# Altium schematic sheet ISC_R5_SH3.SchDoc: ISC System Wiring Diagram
size B; DrawnBy: Filiberto Clara; Engineer: Filiberto Clara; Organization: LIGO Laboratory; Address1: California Institute of Technology; Address2: Massachusetts Institute of Technology; SheetNumber: 21; SheetTotal: 37
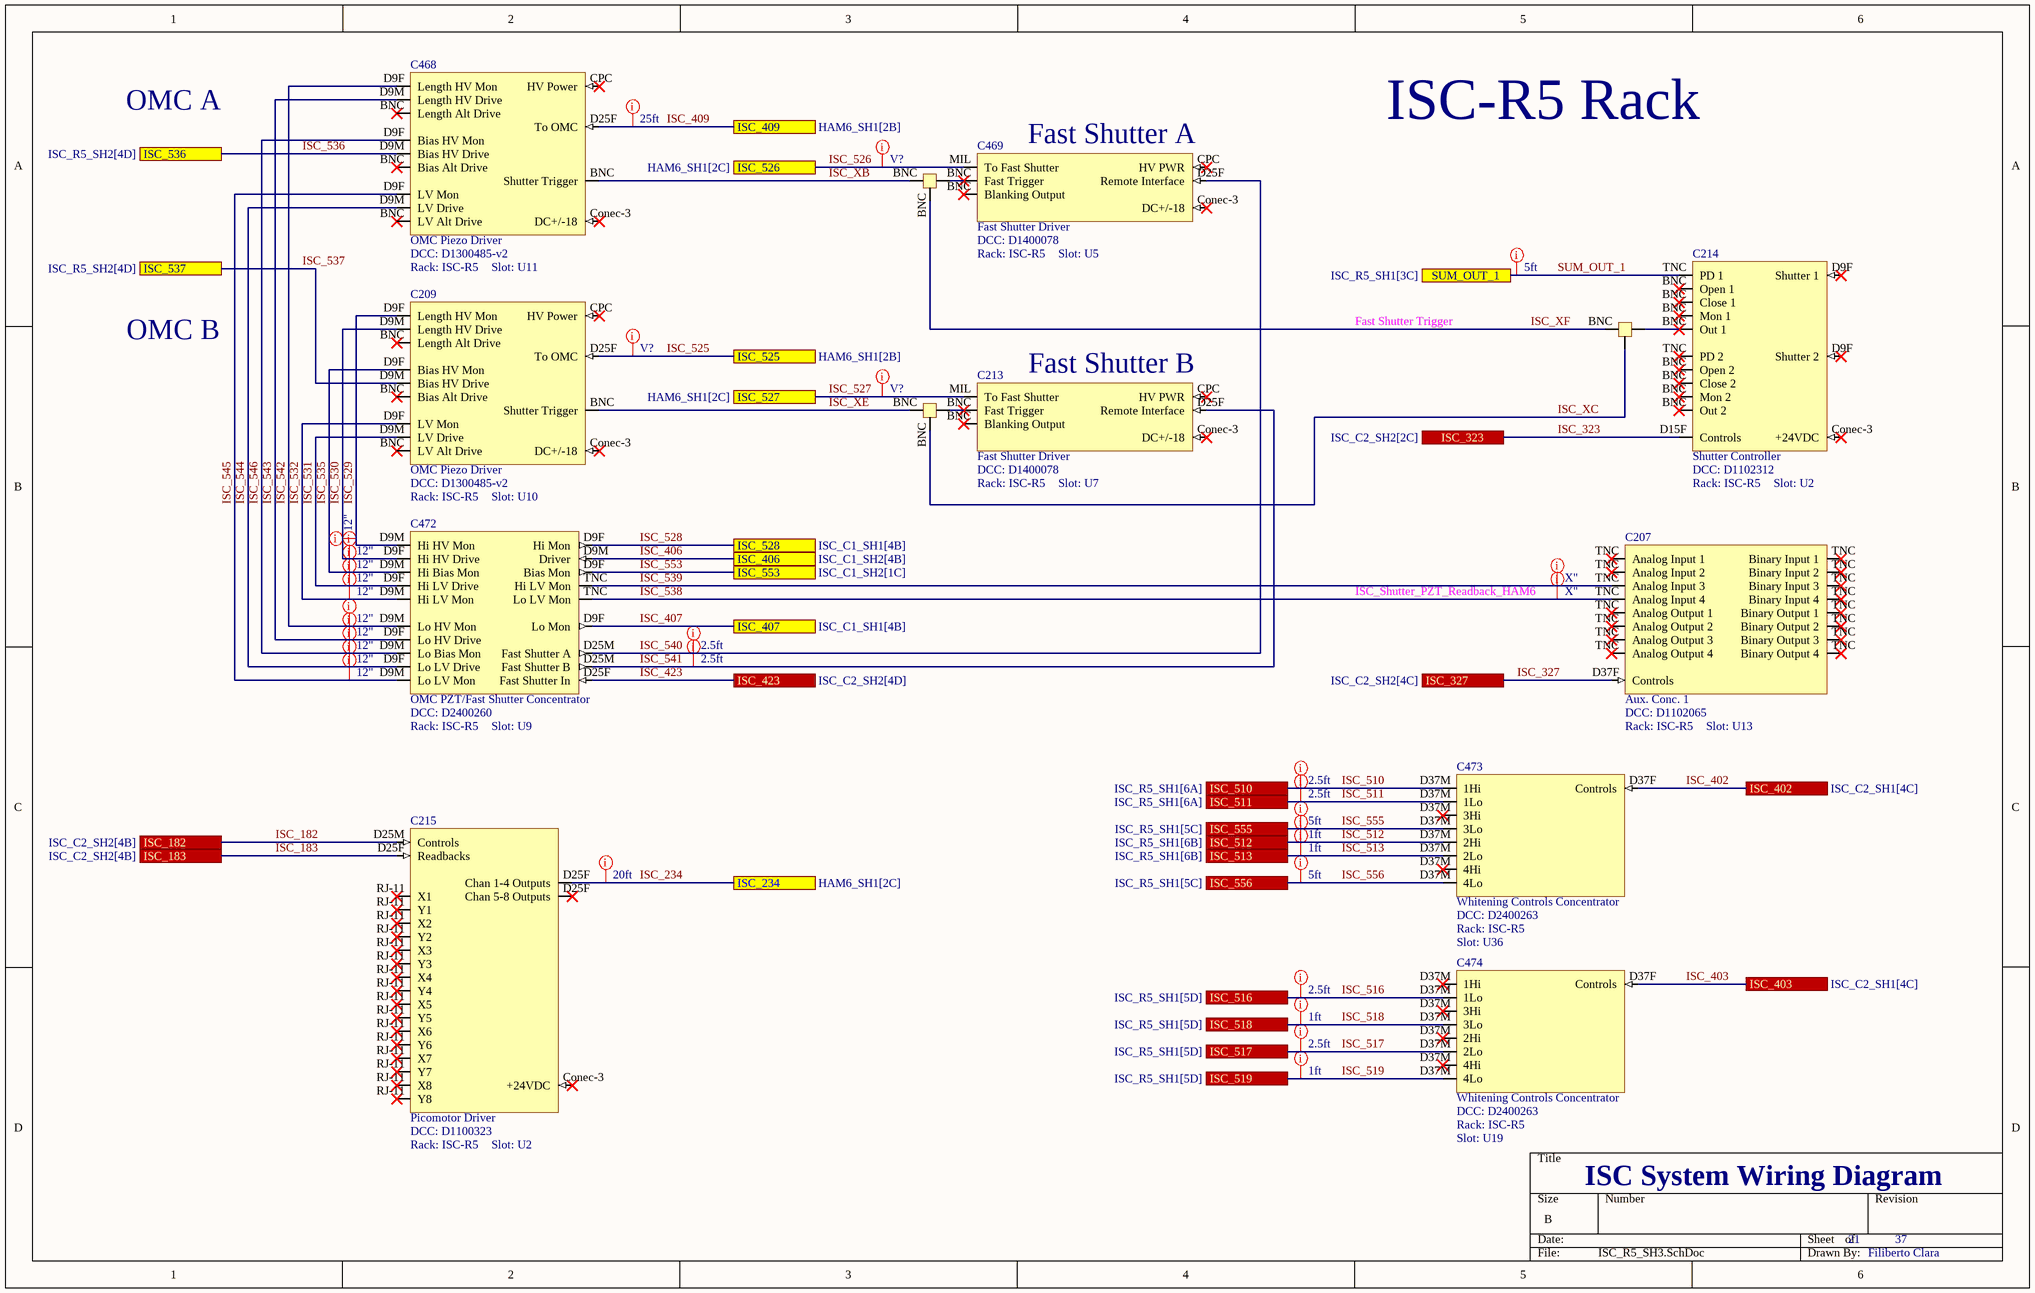
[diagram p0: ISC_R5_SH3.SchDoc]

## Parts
C207  Aux. Conc. 1  DCC: D1102065  Rack: ISC-R5  Slot: U13
C209  OMC Piezo Driver  DCC: D1300485-v2  Rack: ISC-R5  Slot: U10
C213  Fast Shutter Driver  DCC: D1400078  Rack: ISC-R5  Slot: U7
C214  Shutter Controller  DCC: D1102312  Rack: ISC-R5  Slot: U2
C215  Picomotor Driver  DCC: D1100323  Rack: ISC-R5  Slot: U2
C281  Tee  (value not drawn)
C468  OMC Piezo Driver  DCC: D1300485-v2  Rack: ISC-R5  Slot: U11
C469  Fast Shutter Driver  DCC: D1400078  Rack: ISC-R5  Slot: U5
C470  Tee  (value not drawn)
C471  Tee  (value not drawn)
C472  OMC PZT/Fast Shutter Concentrator  DCC: D2400260  Rack: ISC-R5  Slot: U9
C473  Whitening Controls Concentrator  DCC: D2400263  Rack: ISC-R5  Slot: U36
C474  Whitening Controls Concentrator  DCC: D2400263  Rack: ISC-R5  Slot: U19

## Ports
ISC_182 (see ISC_C2_SH2[4B]), ISC_183 (see ISC_C2_SH2[4B]), ISC_234 (see HAM6_SH1[2C]), ISC_323 (see ISC_C2_SH2[2C]), ISC_327 (see ISC_C2_SH2[4C]), ISC_402 (see ISC_C2_SH1[4C]), ISC_403 (see ISC_C2_SH1[4C]), ISC_406 (see ISC_C1_SH2[4B]), ISC_407 (see ISC_C1_SH1[4B]), ISC_409 (see HAM6_SH1[2B]), ISC_423 (see ISC_C2_SH2[4D]), ISC_510 (see ISC_R5_SH1[6A]), ISC_511 (see ISC_R5_SH1[6A]), ISC_512 (see ISC_R5_SH1[6B]), ISC_513 (see ISC_R5_SH1[6B]), ISC_516 (see ISC_R5_SH1[5D]), ISC_517 (see ISC_R5_SH1[5D]), ISC_518 (see ISC_R5_SH1[5D]), ISC_519 (see ISC_R5_SH1[5D]), ISC_525 (see HAM6_SH1[2B]), ISC_526 (see HAM6_SH1[2C]), ISC_527 (see HAM6_SH1[2C]), ISC_528 (see ISC_C1_SH1[4B]), ISC_536 (see ISC_R5_SH2[4D]), ISC_537 (see ISC_R5_SH2[4D]), ISC_553 (see ISC_C1_SH2[1C]), ISC_555 (see ISC_R5_SH1[5C]), ISC_556 (see ISC_R5_SH1[5C]), SUM_OUT_1 (see ISC_R5_SH1[3C])

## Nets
ISC_182: C215.D25M(Controls) ; port ISC_182
ISC_183: C215.D25F(Readbacks) ; port ISC_183
ISC_234: C215.D25F(Chan_1-4_Outputs) ; port ISC_234
ISC_323: C214.D15F(Controls) ; port ISC_323
ISC_327: C207.D37F(Controls) ; port ISC_327
ISC_402: C473.D37F(Controls) ; port ISC_402
ISC_403: C474.D37F(Controls) ; port ISC_403
ISC_406: C472.D9M(Driver) ; port ISC_406
ISC_407: C472.D9F(Lo_Mon) ; port ISC_407
ISC_409: C468.D25F(To_OMC) ; port ISC_409
ISC_423: C472.D25F(Fast_Shutter_In) ; port ISC_423
ISC_510: C473.D37M(1Hi) ; port ISC_510
ISC_511: C473.D37M(1Lo) ; port ISC_511
ISC_512: C473.D37M(2Hi) ; port ISC_512
ISC_513: C473.D37M(2Lo) ; port ISC_513
ISC_516: C474.D37M(1Hi) ; port ISC_516
ISC_517: C474.D37M(2Lo) ; port ISC_517
ISC_518: C474.D37M(3Lo) ; port ISC_518
ISC_519: C474.D37M(4Lo) ; port ISC_519
ISC_525: C209.D25F(To_OMC) ; port ISC_525
ISC_526: C469.MIL(To_Fast_Shutter) ; port ISC_526
ISC_527: C213.MIL(To_Fast_Shutter) ; port ISC_527
ISC_528: C472.D9F(Hi_Mon) ; port ISC_528
ISC_529: C209.D9F(Length_HV_Mon) C472.D9M(Hi_HV_Mon)
ISC_530: C209.D9M(Length_HV_Drive) C472.D9F(Hi_HV_Drive)
ISC_531: C209.D9M(LV_Drive) C472.D9F(Hi_LV_Drive)
ISC_532: C209.D9F(LV_Mon) C472.D9M(Hi_LV_Mon)
ISC_535: C209.D9F(Bias_HV_Mon) C472.D9M(Hi_Bias_Mon)
ISC_536: C468.D9M(Bias_HV_Drive) ; port ISC_536
ISC_537: C209.D9M(Bias_HV_Drive) ; port ISC_537
ISC_538: C207.TNC(Analog_Input_4) C472.TNC(Lo_LV_Mon)
ISC_539: C207.TNC(Analog_Input_1) C472.TNC(Hi_LV_Mon)
ISC_540: C469.D25F(Remote_Interface) C472.D25M(Fast_Shutter_A)
ISC_541: C213.D25F(Remote_Interface) C472.D25M(Fast_Shutter_B)
ISC_542: C468.D9F(Length_HV_Mon) C472.D9M(Lo_HV_Mon)
ISC_543: C468.D9M(Length_HV_Drive) C472.D9F(Lo_HV_Drive)
ISC_544: C468.D9M(LV_Drive) C472.D9F(Lo_LV_Drive)
ISC_545: C468.D9F(LV_Mon) C472.D9M(Lo_LV_Mon)
ISC_546: C468.D9F(Bias_HV_Mon) C472.D9M(Lo_Bias_Mon)
ISC_553: C472.D9F(Bias_Mon) ; port ISC_553
ISC_555: C473.D37M(3Lo) ; port ISC_555
ISC_556: C473.D37M(4Lo) ; port ISC_556
ISC_XB: C468.BNC(Length_Alt_Drive) C470.BNC
ISC_XC: C281.BNC C471.BNC
ISC_XE: C209.BNC(Length_Alt_Drive) C281.BNC
ISC_XF: C470.BNC C471.BNC
SUM_OUT_1: C214.TNC(PD_1) ; port SUM_OUT_1
NetC213_BNC: C213.BNC(Fast_Trigger) C281.BNC
NetC214_BNC: C214.BNC(Open_1) C471.BNC
NetC469_BNC: C469.BNC(Fast_Trigger) C470.BNC

Not connected (* = marked no-connect by the designer): C209 Conec-3(DC+/-18)* CPC(HV_Power)*; C213 Conec-3(DC+/-18)* CPC(HV_PWR)*; C214 Conec-3(+24VDC)* D9F(Shutter_1)*; C215 Conec-3(+24VDC)* RJ-11(X1)*; C468 Conec-3(DC+/-18)* CPC(HV_Power)*; C469 Conec-3(DC+/-18)* CPC(HV_PWR)*

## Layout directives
Length: X": ISC_538, ISC_539
Length: 5ft: ISC_555, ISC_556, SUM_OUT_1
Length: 20ft: ISC_234
Length: 12": ISC_529, ISC_530, ISC_531, ISC_532, ISC_535, ISC_542, ISC_543, ISC_544, ISC_545, ISC_546
Length: 25ft: ISC_409
Length: V?: ISC_525, ISC_526, ISC_527
Length: 2.5ft: ISC_510, ISC_511, ISC_516, ISC_517, ISC_540, ISC_541
Length: 1ft: ISC_512, ISC_513, ISC_518, ISC_519

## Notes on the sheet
- OMC A
- ISC-R5 Rack
- (near C469) Fast Shutter A
- OMC B
- (near C213) Fast Shutter B
- Fast Shutter Trigger
- ISC_Shutter_PZT_Readback_HAM6

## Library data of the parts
C207 = Aux. Conc. 1: Serial: Sxxxxxxx; System: ISC
C209 C468 = OMC Piezo Driver V2: Serial: Sxxxxxxx; System: ISC
C213 C469 = Fast Shutter Driver: Serial: Sxxxxxxx; System: ISC
C214 = Shutter Controller: Serial: Sxxxxxxx; System: ISC
C215 = Picomotor Driver: Serial: Sxxxxxxx; System: ISC
C281 C470 C471 = TNC Tee: Tee (TNC); Serial: Sxxxxxxx; System: ISC; Rack: ISCT?; Slot: U?
C472 = OMC PZT/Fast Shutter Panel: Serial: Sxxxxxxx; System: ISC
C473 C474 = Whitening Controls Concentrator: Serial: Sxxxxxxx; System: ISC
